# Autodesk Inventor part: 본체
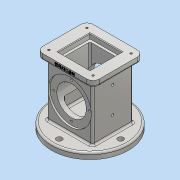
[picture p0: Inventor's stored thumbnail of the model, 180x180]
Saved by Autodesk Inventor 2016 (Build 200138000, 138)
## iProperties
Created: 2018-10
Part Number: 본체
Material: 알루미늄 6061
Document SubType Name: Modeling
Designer: Administrator
Density: 2.7 g/cm^3
Appearance: 알루미늄 - 평지
Mass: 984.817 g
Surface Area: 744.757 cm^2
Volume: 364.747 cm^3
Author: Administrator
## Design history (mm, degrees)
sketch "스케치1"
  geometry: C1 r 62.5 at (0, 0); 1 further point
  constraints: 1 centre point, 1 coincident
  dimensions: "d0" = 125 diameter of C1
extrude "돌출1" new body sketch "스케치1" distance "d1" = 10; taper "d2" = 0 deg
sketch "스케치2"
  geometry: L1 (-37, 33)-(37, 33); L2 (37, 33)-(37, -33); L3 (37, -33)-(-37, -33); L4 (-37, -33)-(-37, 33); L5 (-37, 33)-(37, -33); L6 (37, 33)-(-37, -33); 1 further point
  constraints: 12 end point, 2 midpoint, 2 parallel, 1 horizontal, 1 perpendicular
  dimensions: "d3" = 74 distance of L1.start L1.end; "d4" = 66 distance of L1.end L2.end
extrude "돌출2" join sketch "스케치2" distance "d5" = 88; taper "d6" = 0 deg
sketch "스케치3"
  geometry: L1 (-46, 41)-(46, 41); L2 (46, 41)-(46, -41); L3 (46, -41)-(-46, -41); L4 (-46, -41)-(-46, 41); L5 (-46, 41)-(46, -41); L6 (46, 41)-(-46, -41); 1 further point
  constraints: 12 end point, 2 midpoint, 2 parallel, 1 horizontal, 1 perpendicular
  dimensions: "d7" = 92 distance of L1.start L1.end; "d8" = 82 distance of L1.end L2.end
extrude "돌출3" join sketch "스케치3" distance "d9" = 10; taper "d10" = 0 deg
sketch "스케치4"
  geometry: L1 (-99.391, 54)-(79.093, 54); L2 (-62.5, 0)-(62.5, 0) reference; L3 (0, 145.587)-(0, -32.197) reference; L4 (-33, 10)-(-33, 98) reference; L5 (-33, 54)-(-33, 89); L6 (-30, 89)-(-30, 78); L7 (-30, 78)-(30, 78); L8 (30, 78)-(30, 89); L9 (30, 89)-(33, 89); L10 (33, 10)-(33, 98) reference; L11 (33, 54)-(33, 89); L12 (33, 54)-(-33, 54); L13 (-33, 89)-(-30, 89); 1 further point
  constraints: 20 end point, 3 perpendicular, 3 vertical, 2 collinear, 2 midpoint, 2 point on line, 1 horizontal, 1 parallel
  dimensions: "d11" = 54 distance between parallel lines of L2 L1; "d12" = 70 diameter of L13 L1; "d13" = 48 diameter of L7 L1; "d14" = 70 diameter of L9 L1; "d15" = 3 distance of L5.end L6.start; "d16" = 3 distance of L8.end L9.end
revolve "회전1" sketch "스케치4" stored, may be unused: angle "d17" = 90 deg
sketch "스케치5"
  geometry: 2 further points
hole "구멍1" sketch "스케치5" at (0, 29) diameter "d18" = 3.242; stored, may be unused: countersink angle "d22" = 90 deg, drill point angle "d24" = 118 deg; dims "d19" = 4, "d20" = 4, "d21" = 2, "d23" = 6
sketch "스케치6"
  geometry: L1 (-26, -26)-(-26, 26); L2 (-26, 26)-(26, 26); L3 (26, 26)-(26, -26); L4 (26, -26)-(-26, -26); L5 (-26, -26)-(26, 26); L6 (-26, 26)-(26, -26); L7 (-24, 30)-(24, 30) reference; 1 further point
  constraints: 12 end point, 2 midpoint, 2 parallel, 2 perpendicular
  dimensions: "d31" = 52 distance of L1.start L1.end; "d32" = 52 distance of L1.end L2.end
extrude "돌출4" cut sketch "스케치6" distance "d33" = 8; taper "d34" = 0 deg
sketch "스케치7"
  geometry: L1 (-22, 22)-(22, 22); L2 (22, 22)-(22, -22); L3 (22, -22)-(-22, -22); L4 (-22, -22)-(-22, 22); L5 (-22, 22)-(22, -22); L6 (22, 22)-(-22, -22); 1 further point
  constraints: 12 end point, 2 midpoint, 2 parallel, 1 horizontal, 1 perpendicular
  dimensions: "d35" = 44 distance of L1.start L1.end; "d36" = 44 distance of L1.end L2.end
extrude "돌출5" cut sketch "스케치7" distance "d37" = 74; taper "d38" = 0 deg
sketch "스케치8"
  geometry: L1 (-114.199, 33)-(42.368, 33) reference; L2 (10, -29.5)-(10, 95.5) reference; 2 further points
  constraints: 2 end point, 2 horizontal, 1 point on line
  dimensions: "d39" = 37 distance from line of point (-27, 33) L2
hole "구멍2" sketch "스케치8" at (-27, 33) diameter "d41" = 4.134; stored, may be unused: countersink angle "d45" = 82 deg, drill point angle "d47" = 0 deg; dims "d42" = 10, "d43" = 3.023, "d44" = 2, "d46" = 14.2
sketch "스케치9"
  geometry: L1 (10, -29.5)-(10, 95.5) reference; 2 further points
  dimensions: "d48" = 80 distance from line of point (-70, 33) L1
hole "구멍3" sketch "스케치9" at (-70, 33) diameter "d49" = 4.134; stored, may be unused: countersink angle "d53" = 82 deg, drill point angle "d55" = 0 deg; dims "d50" = 10, "d51" = 3.023, "d52" = 2, "d54" = 14.2
sketch "스케치10"
  geometry: 6 further points
hole "구멍4" sketch "스케치10" at (-36, 31), (36, 31), (36, -31), (-36, -31) diameter "d58" = 3.242; stored, may be unused: countersink angle "d62" = 82 deg, drill point angle "d64" = 0 deg; dims "d59" = 4, "d60" = 3.023, "d61" = 2, "d63" = 6
sketch "스케치11" dims "d65" = 100
  geometry: 3 further points
  constraints: 1 coincident, 1 vertical alignment, 2 other
hole "구멍5" sketch "스케치11" at (0, 50) diameter "d66" = 9; stored, may be unused: countersink angle "d70" = 82 deg, drill point angle "d72" = 0 deg; dims "d67" = 4, "d68" = 3.023, "d69" = 2, "d71" = 10
fillet "모깎기1" dims "d76" = 10
sketch "스케치13"
  geometry: L1 (0, 126.362)-(0, -24.909) reference; L2 (0, 18)-(-24.826, 18); L3 (62.5, 10)-(-62.5, 10) reference; L4 (-62.5, 0)-(62.5, 0) reference; L5 (-24.826, 18)-(-28, 0); L6 (-62.5, 0)-(62.5, 0) reference; L7 (0, 0)-(-28, 0); L8 (0, 0)-(0, 18)
  constraints: 10 end point, 2 collinear, 2 point on line, 2 vertical, 1 horizontal
  dimensions: "d78" = 80 deg angle of L4 L5; "d79" = 56 diameter of L5.end L1; "d80" = 18 distance between parallel lines of L2 L4
revolve "회전2" sketch "스케치13" stored, may be unused: angle "d81" = 90 deg
sketch "스케치14"
  geometry: L1 (-10, 10)-(-10, 0) reference; L2 (72, 0)-(0, 0) reference; L3 (62, 2)-(10, 2) reference; 2 further points
  constraints: 1 other
  dimensions: "d82" = 46 distance from line of L1 point (36, 6); "d85" = 4 distance from line of L3 point (36, 6)
fillet "모깎기2" dims "d84" = 3
feature "엠보싱1" dims "d86" = 0.5, "d87" = 0
fillet "모깎기3" dims "d88" = 3
fillet "모깎기4" dims "d89" = 3
fillet "모깎기5" dims "d90" = 3
fillet "모깎기6" dims "d91" = 3
fillet "모깎기7" dims "d92" = 3
chamfer "모따기2" distance "d96" = 1; stored, may be unused: second distance "d97" = 2, angle "d98" = 45 deg
node "솔리드1"
pattern_circular "원형 패턴1" dims angle "d26" = 360 deg
mirror "대칭1"
pattern_circular "원형 패턴2" dims angle "d29" = 360 deg
pattern_circular "원형 패턴3" dims angle "d74" = 360 deg
node "투영된 루프1"
